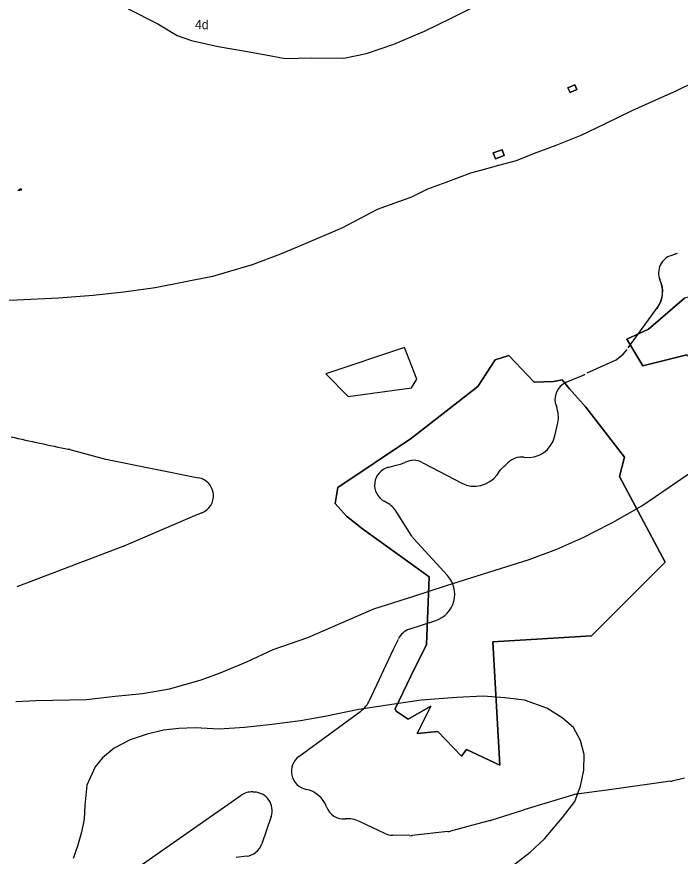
# Model space of a CAD drawing. Extents: x -445049 to -436194, y -1142460 to -1129816.
# Drawn here: x -444397 to -443678, y -1134043 to -1133134 of the extents above; entities that cross this region are included whole.
import ezdxf

# ---------------------------------------------------------------- set-up
doc = ezdxf.new("R2010")
doc.units = 0
for name, color, linetype in [('Vrstva 23', 7, 'Continuous'), ('Vrstva 51', 7, 'Continuous'), ('Vrstva 7', 7, 'Continuous')]:
    doc.layers.add(name, color=color, linetype=linetype)

msp = doc.modelspace()

# ---------------------------------------------------------------- linework, layer by layer
at = {"layer": 'Vrstva 23'}
for p, q in [((-443688.06, -1133392.11), (-443681.15, -1133389.77)), ((-443688.05, -1133392.11), (-443682.51, -1133390.24)), ((-443734.56, -1133492.22), (-443701.99, -1133447.6)), ((-443779.06, -1133519.44), (-443747.47, -1133505.36)), ((-443801.66, -1133529.65), (-443786.04, -1133523.11)), ((-443814.12, -1133587.81), (-443810.94, -1133573.65)), ((-444339.87, -1133602.48), (-444300.96, -1133613.04)), ((-444300.57, -1133613.13), (-444200.21, -1133633.02)), ((-443994.54, -1133621.77), (-443993.72, -1133621.56)), ((-443993.72, -1133621.56), (-443985.96, -1133619.49)), ((-443985.96, -1133619.49), (-443981.51, -1133618.3)), ((-443876.74, -1133629.8), (-443873.21, -1133624.9)), ((-443996.25, -1133660.14), (-443998.99, -1133658.64)), ((-443969.11, -1133696.46), (-443985.19, -1133670.61)), ((-444282.12, -1133707.42), (-444397.22, -1133751.29)), ((-443930.52, -1133739.07), (-443966.87, -1133699.41)), ((-443971.86, -1133797.29), (-443943.23, -1133787.83)), ((-444091.41, -1133935), (-444024.24, -1133885.85)), ((-443688.66, -1133962.04), (-443749.65, -1133970.4)), ((-443673.46, -1133958.73), (-443687.04, -1133961.75)), ((-443749.72, -1133970.41), (-443790.2, -1133975.81)), ((-444260.83, -1134051.85), (-444153.95, -1133977.14)), ((-443795.07, -1133976.88), (-443847.73, -1133993.11)), ((-443847.92, -1133993.17), (-443883.42, -1134004.36)), ((-444121.53, -1134000.09), (-444131.69, -1134029.79)), ((-443998.19, -1134018.59), (-444025.87, -1134005.48)), ((-443884.31, -1134004.61), (-443927.21, -1134015.99)), ((-443930.12, -1134016.54), (-443968.57, -1134020.81)), ((-443971.22, -1134020.92), (-443990.07, -1134020.51)), ((-444148.32, -1134043.19), (-444159.53, -1134044.48))]:
    msp.add_line(p, q, dxfattribs=at)
for points in [[(-444392.96, -1133319.92), (-444395.98, -1133321.72), (-444391.73, -1133320.98), (-444392.45, -1133319.93)], [(-443703.28, -1133449.61), (-443699.82, -1133443.44), (-443698.13, -1133438.25), (-443697.54, -1133434.46), (-443697.54, -1133428.83), (-443697.95, -1133425.04), (-443698.76, -1133422.18), (-443700.24, -1133418.44)], [(-443747.47, -1133505.36), (-443740.11, -1133499.35), (-443735.76, -1133494.27)], [(-443957.98, -1133616.47), (-443947.55, -1133621.91), (-443914.95, -1133638.89)], [(-444196.76, -1133671.25), (-444204.63, -1133674.35), (-444281.26, -1133707.07)], [(-444014.78, -1133874.33), (-443988.78, -1133818.69), (-443983.7, -1133807.82)]]:
    msp.add_lwpolyline(points, dxfattribs=at)
msp.add_lwpolyline([(-444062.25, -1133520.58), (-444038.22, -1133544.98), (-443969.53, -1133535.67), (-443963.56, -1133526.24), (-443976.93, -1133491.98)], close=True, dxfattribs=at)
for centre, radius, start, end in [((-443681.65, -1133411.06), 20, 108.66887, 201.66066), ((-443726.31, -1133431.46), 29.17, 325.3968, 24.55892), ((-443797.62, -1133495.44), 30, 292.71752, 302.27788), ((-443793.94, -1133548.1), 20, 112.71752, 202.28626), ((-443840.2, -1133567.06), 30, 347.31398, 22.28626), ((-443775.03, -1130828.32), 2831.04, 257.17539, 258.46568), ((-443843.39, -1133581.22), 30, 261.89899, 347.31398), ((-444345.11, -1133621.79), 20, 74.81858, 78.46568), ((-444294.54, -1133583.74), 30, 257.64656, 258.41466), ((-443989.22, -1133589.31), 30, 284.90643, 296.10723), ((-443967.22, -1133634.21), 20, 62.47963, 116.10723), ((-443850.44, -1133630.72), 20, 81.89899, 136.84869), ((-443989.38, -1133641.1), 20, 104.93292, 241.28626), ((-443988.57, -1133640.88), 20, 104.92783, 104.93292), ((-443980.81, -1133638.81), 20, 104.90643, 104.92783), ((-443856.98, -1133636.57), 20, 126.78083, 144.27291), ((-443886.91, -1133596.53), 30, 306.78083, 316.84869), ((-444204.1, -1133652.64), 20, 291.51809, 78.78583), ((-443901.09, -1133612.28), 30, 242.48428, 324.27291), ((-444010.67, -1133686.45), 30, 31.87585, 61.28626), ((-443952.13, -1133685.9), 20, 211.87585, 222.50894), ((-444271.43, -1133735.45), 30, 110.71146, 110.86445), ((-444289.12, -1133688.68), 20, 290.71146, 293.12464), ((-443952.64, -1133759.34), 30, 288.28307, 42.50894), ((-443965.58, -1133816.28), 20, 108.28307, 154.96681), ((-444041.96, -1133861.64), 30, 306.1984, 334.95889), ((-444079.59, -1133951.14), 20, 126.1984, 258.49586), ((-443691.38, -1133942.22), 20, 277.80915, 282.52881), ((-444089.57, -1134000.14), 30, 20.34171, 78.49586), ((-443752.37, -1133950.59), 20, 277.595, 277.80915), ((-444142.49, -1133993.53), 20, 87.20232, 124.9539), ((-444134.62, -1133832.55), 141.17, 267.20232, 267.92508), ((-444140.46, -1133993.62), 20, 341.12813, 87.92508), ((-443786.24, -1134005.55), 30, 97.595, 107.1299), ((-444042.68, -1133982.76), 20, 200.34171, 274.55829), ((-443838.9, -1134021.78), 30, 107.1299, 107.4963), ((-444038.71, -1134032.6), 30, 64.6655, 94.55829), ((-443889.44, -1133985.28), 20, 284.8518, 287.4963), ((-443932.33, -1133996.66), 20, 276.33695, 284.8518), ((-443989.63, -1134000.51), 20, 244.6655, 268.74545), ((-443970.78, -1134000.93), 20, 268.74545, 276.33695), ((-444150.61, -1134023.32), 20, 276.5717, 341.12813)]:
    msp.add_arc(centre, radius, start, end, dxfattribs=at)
at = {"layer": 'Vrstva 51'}
for points in [[(-444276.61, -1133124.96), (-444244.19, -1133141.1), (-444223.56, -1133153.86), (-444207.77, -1133159.2), (-444178.79, -1133165.95), (-444147.22, -1133171.23), (-444121.42, -1133176.07), (-444106.27, -1133178.87), (-444077.98, -1133178.09), (-444042.7, -1133178.26), (-444018.25, -1133173.45), (-443988.42, -1133163.24), (-443955.38, -1133149.11), (-443926.51, -1133135.09), (-443888.12, -1133115.97)], [(-443662.98, -1133204.49), (-443682.93, -1133214.04), (-443704.96, -1133223.85), (-443730.8, -1133235.41), (-443760.14, -1133249.99), (-443786.05, -1133262.37), (-443813.05, -1133273.03), (-443836.64, -1133281.9), (-443856.07, -1133289.86), (-443875.25, -1133294.56), (-443890.74, -1133299.12), (-443905.36, -1133302.94), (-443932.33, -1133313.19), (-443952.1, -1133320.3), (-443969.56, -1133329.22), (-444006.58, -1133342.4), (-444044.08, -1133362.1), (-444086.48, -1133380.24), (-444111.56, -1133390.69), (-444142.12, -1133402.28), (-444185.1, -1133414.85), (-444247.41, -1133427.34), (-444281.2, -1133432.02), (-444314.4, -1133435.7), (-444352.17, -1133438.52), (-444397.1, -1133440.8), (-444432.19, -1133442.27)], [(-444398.4, -1133875.42), (-444376.72, -1133874.47), (-444321.6, -1133873.47), (-444290.44, -1133869.64), (-444260.9, -1133866.72), (-444231.71, -1133861.71), (-444198.6, -1133852.37), (-444177.44, -1133844.7), (-444147.17, -1133832.06), (-444119.45, -1133819.22), (-444081.94, -1133806.09), (-444010.15, -1133774.97), (-443967.99, -1133761.67), (-443931.66, -1133749.94), (-443878.92, -1133733.39), (-443842.03, -1133721.76), (-443811.88, -1133710.65), (-443782.58, -1133697.42), (-443755.05, -1133683.5), (-443751.57, -1133681.74), (-443719.85, -1133663.55), (-443690.02, -1133643.16), (-443659.09, -1133621.82)], [(-443859.8, -1134053.79), (-443840.66, -1134038.76), (-443825.18, -1134024.49), (-443805.94, -1134001.25), (-443792.28, -1133983.75), (-443786.41, -1133967.22), (-443782.54, -1133950.02), (-443782.3, -1133933.06), (-443786.3, -1133917.84), (-443793.99, -1133903.88), (-443806.05, -1133893.2), (-443822.75, -1133882.69), (-443846.81, -1133874.19), (-443868.22, -1133871.55), (-443891.9, -1133869.77), (-443920.15, -1133871.25), (-443958.94, -1133873.99), (-443995.37, -1133879.48), (-444026.6, -1133884.34), (-444063.18, -1133891.87), (-444089.77, -1133896.56), (-444123.52, -1133900.71), (-444150.51, -1133903.83), (-444177.89, -1133905.37), (-444204.02, -1133903.92), (-444221.57, -1133904.66), (-444238.17, -1133906.5), (-444255.98, -1133910.82), (-444274.47, -1133917.14), (-444291.6, -1133926.15), (-444304.22, -1133936.51), (-444312.15, -1133946.21), (-444321.36, -1133966.09), (-444323.52, -1133988.05), (-444324.13, -1134002.93), (-444327.25, -1134017.1), (-444331.48, -1134032.21), (-444336.1, -1134045.76)]]:
    msp.add_lwpolyline(points, dxfattribs=at)
at = {"layer": 'Vrstva 7'}
msp.add_line((-443863.86, -1133500.79), (-443836.61, -1133529.61), dxfattribs=at)
for points in [[(-443799.94, -1133210.75), (-443797.65, -1133215.75), (-443790.07, -1133212.29), (-443792.36, -1133207.28)], [(-443871.22, -1133277.73), (-443880.77, -1133281.16), (-443878.49, -1133287.47), (-443868.95, -1133284.04)]]:
    msp.add_lwpolyline(points, close=True, dxfattribs=at)
for points in [[(-443799.94, -1133210.75), (-443792.36, -1133207.28), (-443790.07, -1133212.29), (-443797.65, -1133215.75), (-443799.94, -1133210.75)], [(-443797.65, -1133215.75), (-443799.94, -1133210.75), (-443792.36, -1133207.28), (-443790.07, -1133212.29), (-443797.65, -1133215.75)], [(-443792.36, -1133207.28), (-443790.07, -1133212.29), (-443797.65, -1133215.75), (-443799.94, -1133210.75), (-443792.36, -1133207.28)], [(-443871.22, -1133277.73), (-443868.95, -1133284.04), (-443878.49, -1133287.47), (-443880.77, -1133281.16), (-443871.22, -1133277.73)], [(-443868.95, -1133284.04), (-443878.49, -1133287.47), (-443880.77, -1133281.16), (-443871.22, -1133277.73), (-443868.95, -1133284.04)], [(-443871.22, -1133277.73), (-443868.95, -1133284.04), (-443878.49, -1133287.47), (-443880.77, -1133281.16), (-443871.22, -1133277.73)], [(-443583.42, -1133456.82), (-443598.49, -1133433.35), (-443625.9, -1133453.62), (-443637.96, -1133466.07), (-443662.46, -1133435.54), (-443673.74, -1133438.51), (-443712.48, -1133472.09), (-443735.9, -1133482.79), (-443718.75, -1133511.94), (-443671.06, -1133499.83), (-443667.96, -1133502.28), (-443664.29, -1133522.9), (-443644.48, -1133522.78), (-443639.98, -1133535.76), (-443548.33, -1133525.61)], [(-443671.06, -1133499.83), (-443718.75, -1133511.94), (-443735.9, -1133482.79), (-443712.48, -1133472.09), (-443673.74, -1133438.51)], [(-443671.06, -1133499.83), (-443718.75, -1133511.94), (-443735.9, -1133482.79), (-443712.48, -1133472.09), (-443673.74, -1133438.51)], [(-443671.06, -1133499.83), (-443718.75, -1133511.94), (-443735.9, -1133482.79), (-443712.48, -1133472.09), (-443673.74, -1133438.51)], [(-443863.86, -1133500.79), (-443878.69, -1133505.23), (-443897.51, -1133534.39), (-443969.57, -1133590.16), (-444049.1, -1133643.61), (-444052.09, -1133661.03), (-444039.72, -1133674.81), (-444022.52, -1133688.35), (-443950.37, -1133740.44), (-443953.02, -1133813.77), (-443970.09, -1133847.94), (-443986.96, -1133883.53), (-443986.15, -1133886.17), (-443972.95, -1133894.85), (-443948.63, -1133880.47), (-443963.17, -1133910.14), (-443940.8, -1133907.99), (-443915.07, -1133934.61), (-443909.68, -1133927.41), (-443873.65, -1133944.38), (-443881.2, -1133810.95), (-443774.38, -1133804.55), (-443694.38, -1133724.55), (-443743.96, -1133631.59), (-443738.76, -1133610.8), (-443780.34, -1133556.54), (-443798.13, -1133536.81), (-443806.28, -1133526.88), (-443815.47, -1133528.92), (-443836.61, -1133529.61)], [(-443836.47, -1133529.61), (-443815.47, -1133528.92), (-443806.28, -1133526.88), (-443798.13, -1133536.81), (-443780.34, -1133556.54), (-443738.76, -1133610.8), (-443743.96, -1133631.59), (-443694.38, -1133724.55), (-443774.38, -1133804.55), (-443881.2, -1133810.95), (-443873.65, -1133944.38), (-443909.68, -1133927.41), (-443915.07, -1133934.61), (-443940.8, -1133907.99), (-443963.17, -1133910.14), (-443948.63, -1133880.47), (-443972.95, -1133894.85), (-443986.15, -1133886.17), (-443986.96, -1133883.53), (-443970.09, -1133847.94), (-443953.02, -1133813.77), (-443950.37, -1133740.44), (-444022.52, -1133688.35), (-444039.72, -1133674.81), (-444052.09, -1133661.03), (-444049.1, -1133643.61), (-443969.57, -1133590.16), (-443897.51, -1133534.39), (-443878.69, -1133505.23), (-443863.86, -1133500.79), (-443836.61, -1133529.61), (-443836.47, -1133529.61)], [(-443836.47, -1133529.61), (-443815.47, -1133528.92), (-443806.28, -1133526.88), (-443798.13, -1133536.81), (-443780.34, -1133556.54), (-443738.76, -1133610.8), (-443743.96, -1133631.59), (-443694.38, -1133724.55), (-443774.38, -1133804.55), (-443881.2, -1133810.95), (-443873.65, -1133944.38), (-443909.68, -1133927.41), (-443915.07, -1133934.61), (-443940.8, -1133907.99), (-443963.17, -1133910.14), (-443948.63, -1133880.47), (-443972.95, -1133894.85), (-443986.15, -1133886.17), (-443986.96, -1133883.53), (-443970.09, -1133847.94), (-443953.02, -1133813.77), (-443950.37, -1133740.44), (-444022.52, -1133688.35), (-444039.72, -1133674.81), (-444052.09, -1133661.03), (-444049.1, -1133643.61), (-443969.57, -1133590.16), (-443897.51, -1133534.39), (-443878.69, -1133505.23), (-443863.86, -1133500.79), (-443836.61, -1133529.61), (-443836.47, -1133529.61)], [(-443836.47, -1133529.61), (-443815.47, -1133528.92), (-443806.28, -1133526.88), (-443798.13, -1133536.81), (-443780.34, -1133556.54), (-443738.76, -1133610.8), (-443743.96, -1133631.59), (-443694.38, -1133724.55), (-443774.38, -1133804.55), (-443881.2, -1133810.95), (-443873.65, -1133944.38), (-443909.68, -1133927.41), (-443915.07, -1133934.61), (-443940.8, -1133907.99), (-443963.17, -1133910.14), (-443948.63, -1133880.47), (-443972.95, -1133894.85), (-443986.15, -1133886.17), (-443986.96, -1133883.53), (-443970.09, -1133847.94), (-443953.02, -1133813.77), (-443950.37, -1133740.44), (-444022.52, -1133688.35), (-444039.72, -1133674.81), (-444052.09, -1133661.03), (-444049.1, -1133643.61), (-443969.57, -1133590.16), (-443897.51, -1133534.39), (-443878.69, -1133505.23), (-443863.86, -1133500.79), (-443836.61, -1133529.61), (-443836.47, -1133529.61)], [(-443969.57, -1133590.16), (-443897.51, -1133534.39)], [(-443836.47, -1133529.61), (-443815.47, -1133528.92), (-443806.28, -1133526.88), (-443798.13, -1133536.81), (-443780.34, -1133556.54), (-443738.76, -1133610.8), (-443743.96, -1133631.59)], [(-443743.96, -1133631.59), (-443694.38, -1133724.55), (-443774.38, -1133804.55), (-443881.2, -1133810.95), (-443873.65, -1133944.38), (-443909.68, -1133927.41), (-443915.07, -1133934.61), (-443940.8, -1133907.99), (-443963.17, -1133910.14), (-443948.63, -1133880.47), (-443972.95, -1133894.85), (-443986.15, -1133886.17), (-443986.96, -1133883.53), (-443970.09, -1133847.94), (-443953.02, -1133813.77)]]:
    msp.add_lwpolyline(points, dxfattribs=at)

# ---------------------------------------------------------------- texts
at = {"layer": 'Vrstva 51'}
msp.add_text('4d', height=10, dxfattribs=at).set_placement((-444204.17, -1133147.08))

doc.saveas('drawing.dxf')
